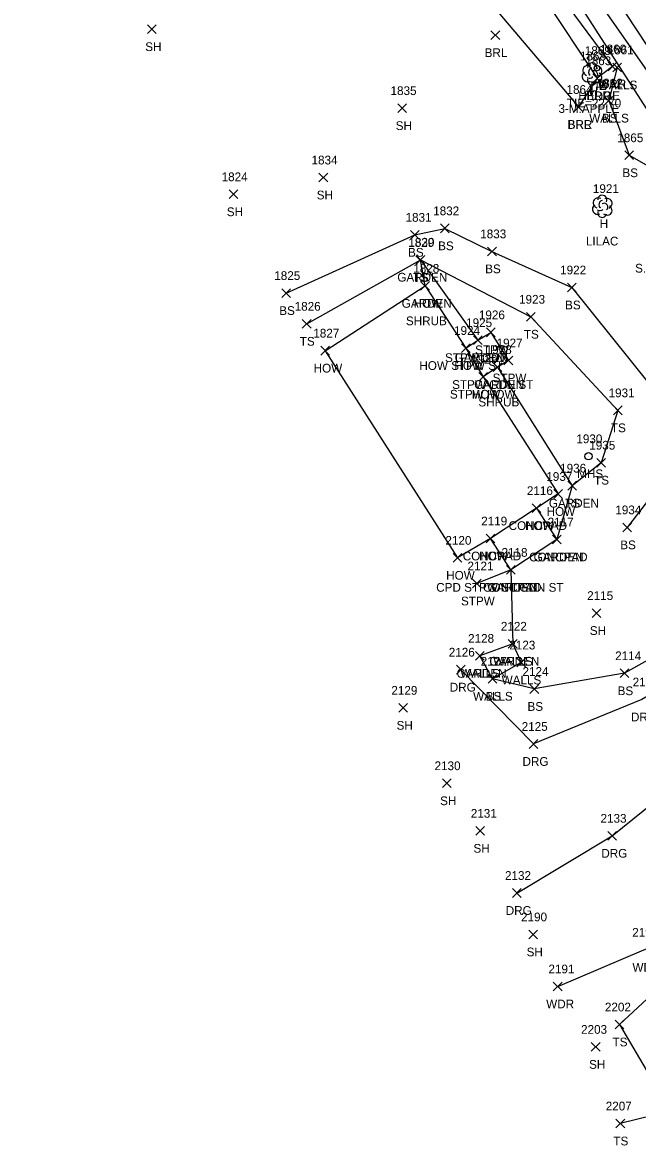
# Model space of a CAD drawing. Extents: x 1501299 to 1502485, y 381423 to 383765.
# Drawn here: x 1501332.8 to 1501473.5, y 383241.3 to 383498.2 of the extents above; entities that cross this region are included whole.
import ezdxf

# ---------------------------------------------------------------- set-up
doc = ezdxf.new("R2010")
doc.units = 0
for name, color, linetype in [('C_A', 7, 'Continuous'), ('C_C', 7, 'Continuous'), ('C_I', 7, 'Continuous'), ('CBP', 7, 'Continuous'), ('L_A', 7, 'Continuous'), ('L_C', 7, 'Continuous'), ('L_I', 7, 'Continuous'), ('L_TIC', 7, 'Continuous'), ('LABL', 7, 'Continuous'), ('LAHR', 7, 'Continuous'), ('LAPB', 7, 'Continuous'), ('LAWA', 7, 'Continuous'), ('LBC', 7, 'Continuous'), ('LBF', 7, 'Continuous'), ('LELB', 7, 'Continuous'), ('LS', 7, 'Continuous'), ('LTD', 7, 'Continuous'), ('LWS', 7, 'Continuous'), ('PET', 7, 'Continuous'), ('R_A', 7, 'Continuous'), ('R_I', 7, 'Continuous'), ('R_TIC', 7, 'Continuous'), ('RDG', 7, 'Continuous'), ('U_A', 7, 'Continuous'), ('U_I', 7, 'Continuous'), ('USMH', 7, 'Continuous')]:
    doc.layers.add(name, color=color, linetype=linetype)

msp = doc.modelspace()

# ---------------------------------------------------------------- linework, layer by layer
at = {"layer": 'CBP'}
for radius in [0.625, 0.0833]:
    msp.add_circle((1501464.19, 383487.75), radius, dxfattribs=at)
at = {"layer": 'L_TIC'}
for points in [[(1501361.38, 383495.65), (1501363.38, 383497.65)], [(1501363.38, 383495.65), (1501361.38, 383497.65)], [(1501439.97, 383494.28), (1501441.97, 383496.28)], [(1501441.97, 383494.28), (1501439.97, 383496.28)], [(1501466.78, 383487.13), (1501468.78, 383489.13)], [(1501468.78, 383487.13), (1501466.78, 383489.13)], [(1501467.85, 383486.89), (1501469.85, 383488.89)], [(1501469.85, 383486.89), (1501467.85, 383488.89)], [(1501463.27, 383484.42), (1501465.27, 383486.42)], [(1501465.27, 383484.42), (1501463.27, 383486.42)], [(1501463.27, 383484.42), (1501465.27, 383486.42)], [(1501465.27, 383484.42), (1501463.27, 383486.42)], [(1501418.68, 383477.59), (1501420.68, 383479.59)], [(1501420.68, 383477.59), (1501418.68, 383479.59)], [(1501458.99, 383477.86), (1501460.99, 383479.86)], [(1501460.99, 383477.86), (1501458.99, 383479.86)], [(1501458.99, 383477.86), (1501460.99, 383479.86)], [(1501460.99, 383477.86), (1501458.99, 383479.86)], [(1501465.9, 383479.31), (1501467.9, 383481.31)], [(1501467.9, 383479.31), (1501465.9, 383481.31)], [(1501465.9, 383479.31), (1501467.9, 383481.31)], [(1501467.9, 383479.31), (1501465.9, 383481.31)], [(1501470.6, 383466.81), (1501472.6, 383468.81)], [(1501472.6, 383466.81), (1501470.6, 383468.81)], [(1501400.61, 383461.72), (1501402.61, 383463.72)], [(1501402.61, 383461.72), (1501400.61, 383463.72)], [(1501380.04, 383457.89), (1501382.04, 383459.89)], [(1501382.04, 383457.89), (1501380.04, 383459.89)], [(1501428.44, 383450.1), (1501430.44, 383452.1)], [(1501430.44, 383450.1), (1501428.44, 383452.1)], [(1501421.55, 383448.61), (1501423.55, 383450.61)], [(1501423.55, 383448.61), (1501421.55, 383450.61)], [(1501439.2, 383444.83), (1501441.2, 383446.83)], [(1501441.2, 383444.83), (1501439.2, 383446.83)], [(1501422.74, 383442.85), (1501424.74, 383444.85)], [(1501424.74, 383442.85), (1501422.74, 383444.85)], [(1501422.87, 383442.92), (1501424.87, 383444.92)], [(1501424.87, 383442.92), (1501422.87, 383444.92)], [(1501422.87, 383442.92), (1501424.87, 383444.92)], [(1501424.87, 383442.92), (1501422.87, 383444.92)], [(1501423.88, 383436.94), (1501425.88, 383438.94)], [(1501425.88, 383436.94), (1501423.88, 383438.94)], [(1501423.88, 383436.94), (1501425.88, 383438.94)], [(1501425.88, 383436.94), (1501423.88, 383438.94)], [(1501457.48, 383436.57), (1501459.48, 383438.57)], [(1501459.48, 383436.57), (1501457.48, 383438.57)], [(1501392.09, 383435.29), (1501394.09, 383437.29)], [(1501394.09, 383435.29), (1501392.09, 383437.29)], [(1501448.08, 383429.87), (1501450.08, 383431.87)], [(1501450.08, 383429.87), (1501448.08, 383431.87)], [(1501396.81, 383428.26), (1501398.81, 383430.26)], [(1501398.81, 383428.26), (1501396.81, 383430.26)], [(1501438.94, 383426.31), (1501440.94, 383428.31)], [(1501440.94, 383426.31), (1501438.94, 383428.31)], [(1501435.98, 383424.52), (1501437.98, 383426.52)], [(1501437.98, 383424.52), (1501435.98, 383426.52)], [(1501435.98, 383424.52), (1501437.98, 383426.52)], [(1501437.98, 383424.52), (1501435.98, 383426.52)], [(1501401.01, 383422.12), (1501403.01, 383424.12)], [(1501403.01, 383422.12), (1501401.01, 383424.12)], [(1501401.01, 383422.12), (1501403.01, 383424.12)], [(1501403.01, 383422.12), (1501401.01, 383424.12)], [(1501433.21, 383422.72), (1501435.21, 383424.72)], [(1501435.21, 383422.72), (1501433.21, 383424.72)], [(1501433.21, 383422.72), (1501435.21, 383424.72)], [(1501435.21, 383422.72), (1501433.21, 383424.72)], [(1501442.94, 383419.88), (1501444.94, 383421.88)], [(1501444.94, 383419.88), (1501442.94, 383421.88)], [(1501437.21, 383416.16), (1501439.21, 383418.16)], [(1501439.21, 383416.16), (1501437.21, 383418.16)], [(1501437.21, 383416.16), (1501439.21, 383418.16)], [(1501439.21, 383416.16), (1501437.21, 383418.16)], [(1501440.46, 383418.37), (1501442.46, 383420.37)], [(1501442.46, 383418.37), (1501440.46, 383420.37)], [(1501440.46, 383418.37), (1501442.46, 383420.37)], [(1501442.46, 383418.37), (1501440.46, 383420.37)], [(1501468, 383408.47), (1501470, 383410.47)], [(1501470, 383408.47), (1501468, 383410.47)], [(1501464.15, 383396.49), (1501466.15, 383398.49)], [(1501466.15, 383396.49), (1501464.15, 383398.49)], [(1501457.54, 383391.24), (1501459.54, 383393.24)], [(1501459.54, 383391.24), (1501457.54, 383393.24)], [(1501457.54, 383391.24), (1501459.54, 383393.24)], [(1501459.54, 383391.24), (1501457.54, 383393.24)], [(1501454.32, 383389.34), (1501456.32, 383391.34)], [(1501456.32, 383389.34), (1501454.32, 383391.34)], [(1501449.36, 383386.1), (1501451.36, 383388.1)], [(1501451.36, 383386.1), (1501449.36, 383388.1)], [(1501449.36, 383386.1), (1501451.36, 383388.1)], [(1501451.36, 383386.1), (1501449.36, 383388.1)], [(1501470.1, 383381.7), (1501472.1, 383383.7)], [(1501472.1, 383381.7), (1501470.1, 383383.7)], [(1501438.87, 383379.15), (1501440.87, 383381.15)], [(1501440.87, 383379.15), (1501438.87, 383381.15)], [(1501438.87, 383379.15), (1501440.87, 383381.15)], [(1501440.87, 383379.15), (1501438.87, 383381.15)], [(1501454.06, 383378.92), (1501456.06, 383380.92)], [(1501456.06, 383378.92), (1501454.06, 383380.92)], [(1501454.06, 383378.92), (1501456.06, 383380.92)], [(1501456.06, 383378.92), (1501454.06, 383380.92)], [(1501431.33, 383374.73), (1501433.33, 383376.73)], [(1501433.33, 383374.73), (1501431.33, 383376.73)], [(1501431.33, 383374.73), (1501433.33, 383376.73)], [(1501433.33, 383374.73), (1501431.33, 383376.73)], [(1501443.51, 383371.98), (1501445.51, 383373.98)], [(1501445.51, 383371.98), (1501443.51, 383373.98)], [(1501443.51, 383371.98), (1501445.51, 383373.98)], [(1501445.51, 383371.98), (1501443.51, 383373.98)], [(1501443.51, 383371.98), (1501445.51, 383373.98)], [(1501445.51, 383371.98), (1501443.51, 383373.98)], [(1501435.72, 383368.86), (1501437.72, 383370.86)], [(1501437.72, 383368.86), (1501435.72, 383370.86)], [(1501463.09, 383362.1), (1501465.09, 383364.1)], [(1501465.09, 383362.1), (1501463.09, 383364.1)], [(1501443.93, 383355.08), (1501445.93, 383357.08)], [(1501445.93, 383355.08), (1501443.93, 383357.08)], [(1501443.93, 383355.08), (1501445.93, 383357.08)], [(1501445.93, 383355.08), (1501443.93, 383357.08)], [(1501436.42, 383352.31), (1501438.42, 383354.31)], [(1501438.42, 383352.31), (1501436.42, 383354.31)], [(1501436.42, 383352.31), (1501438.42, 383354.31)], [(1501438.42, 383352.31), (1501436.42, 383354.31)], [(1501445.87, 383350.78), (1501447.87, 383352.78)], [(1501447.87, 383350.78), (1501445.87, 383352.78)], [(1501439.32, 383347.07), (1501441.32, 383349.07)], [(1501441.32, 383347.07), (1501439.32, 383349.07)], [(1501439.32, 383347.07), (1501441.32, 383349.07)], [(1501441.32, 383347.07), (1501439.32, 383349.07)], [(1501469.5, 383348.33), (1501471.5, 383350.33)], [(1501471.5, 383348.33), (1501469.5, 383350.33)], [(1501448.88, 383344.74), (1501450.88, 383346.74)], [(1501450.88, 383344.74), (1501448.88, 383346.74)], [(1501418.88, 383340.42), (1501420.88, 383342.42)], [(1501420.88, 383340.42), (1501418.88, 383342.42)], [(1501428.84, 383323.17), (1501430.84, 383325.17)], [(1501430.84, 383323.17), (1501428.84, 383325.17)], [(1501436.47, 383312.29), (1501438.47, 383314.29)], [(1501438.47, 383312.29), (1501436.47, 383314.29)], [(1501448.63, 383288.59), (1501450.63, 383290.59)], [(1501450.63, 383288.59), (1501448.63, 383290.59)], [(1501454.23, 383276.69), (1501456.23, 383278.69)], [(1501456.23, 383276.69), (1501454.23, 383278.69)], [(1501468.37, 383267.99), (1501470.37, 383269.99)], [(1501470.37, 383267.99), (1501468.37, 383269.99)], [(1501462.92, 383262.87), (1501464.92, 383264.87)], [(1501464.92, 383262.87), (1501462.92, 383264.87)], [(1501468.56, 383245.34), (1501470.56, 383247.34)], [(1501470.56, 383245.34), (1501468.56, 383247.34)]]:
    msp.add_lwpolyline(points, dxfattribs=at)
at = {"layer": 'LABL'}
for points in [[(1501349.77, 383634.07), (1501358.61, 383636.91), (1501365.75, 383641.19), (1501375.86, 383617.1), (1501401.99, 383582.97), (1501432.56, 383539.71), (1501454.75, 383505.78), (1501467.78, 383488.13), (1501464.27, 383485.42), (1501459.99, 383478.86)], [(1501365.08, 383604.09), (1501372.27, 383598.02), (1501384.53, 383567.86), (1501459.99, 383478.86)]]:
    msp.add_lwpolyline(points, dxfattribs=at)
at = {"layer": 'LAHR'}
msp.add_lwpolyline([(1501432.56, 383539.71), (1501451.98, 383503.96), (1501464.27, 383485.42)], dxfattribs=at)
at = {"layer": 'LAPB'}
for points in [[(1501424.88, 383437.94), (1501423.87, 383443.92), (1501436.98, 383425.52)], [(1501441.46, 383419.37), (1501458.54, 383392.24), (1501455.06, 383379.92)], [(1501444.51, 383372.98), (1501444.93, 383356.08), (1501437.42, 383353.31)]]:
    msp.add_lwpolyline(points, dxfattribs=at)
at = {"layer": 'LAWA'}
msp.add_lwpolyline([(1501455.23, 383277.69), (1501474.97, 383286.07), (1501488.16, 383291.02), (1501505.3, 383294.67), (1501520.54, 383293.34), (1501529.9, 383294.53), (1501540.9, 383298.82), (1501560.18, 383293.04)], dxfattribs=at)
at = {"layer": 'LBC'}
for points in [[(1501402.01, 383423.12), (1501424.88, 383437.94), (1501434.21, 383423.72), (1501438.21, 383417.16), (1501455.32, 383390.34), (1501450.36, 383387.1), (1501439.87, 383380.15), (1501432.33, 383375.73)], [(1501402.01, 383423.12), (1501432.33, 383375.73)]]:
    msp.add_lwpolyline(points, dxfattribs=at)
at = {"layer": 'LBF'}
for points in [[(1501434.21, 383423.72), (1501436.98, 383425.52), (1501439.94, 383427.31), (1501443.94, 383420.88), (1501441.46, 383419.37), (1501438.21, 383417.16)], [(1501444.51, 383372.98), (1501436.72, 383369.86)]]:
    msp.add_lwpolyline(points, dxfattribs=at)
at = {"layer": 'LELB'}
for points in [[(1501332.79, 383719.08), (1501356.21, 383681.5), (1501373.29, 383652.69), (1501388.57, 383624.23), (1501410.59, 383588.65), (1501439.07, 383543.46), (1501460.07, 383509.46), (1501480.49, 383480.19), (1501499.63, 383452.74), (1501519.17, 383422.52), (1501533.38, 383399.88)], [(1501410.59, 383588.65), (1501435.97, 383541.32), (1501457.1, 383507.19), (1501476.16, 383477.48), (1501479.31, 383471.05), (1501488.94, 383457.91)], [(1501466.9, 383480.31), (1501471.6, 383467.81), (1501488.94, 383457.91), (1501495.79, 383450.81), (1501515.89, 383421.07), (1501517.94, 383408.26), (1501520.75, 383388.81), (1501512.36, 383377.31), (1501492.52, 383361.6), (1501470.5, 383349.33), (1501449.88, 383345.74), (1501440.32, 383348.07)], [(1501393.09, 383436.29), (1501422.55, 383449.61), (1501429.44, 383451.1), (1501440.2, 383445.83), (1501458.48, 383437.57), (1501476.43, 383415.16), (1501477.31, 383390.7), (1501471.1, 383382.7)], [(1501397.81, 383429.26), (1501423.74, 383443.85), (1501423.87, 383443.92), (1501449.08, 383430.87), (1501469, 383409.47), (1501465.15, 383397.49), (1501458.54, 383392.24)], [(1501529.79, 383319.02), (1501508.47, 383318.79), (1501498.45, 383314.16), (1501488.16, 383291.02), (1501493.84, 383282.99), (1501477.76, 383276.8), (1501469.37, 383268.99), (1501481.01, 383249.17), (1501469.56, 383246.34)]]:
    msp.add_lwpolyline(points, dxfattribs=at)
at = {"layer": 'LS'}
msp.add_lwpolyline([(1501450.36, 383387.1), (1501455.06, 383379.92), (1501444.51, 383372.98), (1501439.87, 383380.15)], dxfattribs=at)
at = {"layer": 'LTD'}
for p, q in [((1501463.06, 383486.5), (1501463.06, 383486.5)), ((1501463.06, 383486.5), (1501463.06, 383486.5)), ((1501465.41, 383456.18), (1501465.41, 383456.18)), ((1501465.41, 383456.18), (1501465.41, 383456.18))]:
    msp.add_line(p, q, dxfattribs=at)
for centre in [(1501463.11, 383487.94), (1501465.45, 383457.62)]:
    msp.add_arc(centre, 1.05, 335.5272, 180.9563, dxfattribs=at)
for centre, major_axis, ratio, start_param, end_param in [((1501462.27, 383487.17), (1.21, -0.51), 0.895232, 1.570796, 4.712389), ((1501462.85, 383486.96), (-0.208, -0.792), 0.645439, 3.141593, 6.283185), ((1501463.56, 383486.34), (-0.5, 0.667), 0.989748, 3.141593, 6.283185), ((1501464.1, 383487.09), (-1.14, -0.48), 0.949671, 1.570796, 4.712389), ((1501461.98, 383485.8), (0.58, -1.04), 0.959034, 3.141593, 6.283185), ((1501463.06, 383485), (0.26, 1.06), 0.942809, 1.570796, 4.712389), ((1501462.6, 383485.75), (-0.625, -0.083), 0.423636, 0, 3.141593), ((1501464.06, 383485.67), (-1.09, 0.79), 0.841452, 1.570796, 4.712389), ((1501464.32, 383455.47), (0.58, -1.04), 0.959034, 3.141593, 6.283185), ((1501464.62, 383456.85), (1.21, -0.51), 0.895232, 1.570796, 4.712389), ((1501465.2, 383456.64), (-0.208, -0.792), 0.645439, 3.141593, 6.283185), ((1501465.91, 383456.01), (-0.5, 0.667), 0.989748, 3.141593, 6.283185), ((1501466.45, 383456.76), (-1.14, -0.48), 0.949671, 1.570796, 4.712389), ((1501465.41, 383454.68), (0.26, 1.06), 0.942809, 1.570796, 4.712389), ((1501464.95, 383455.43), (-0.625, -0.083), 0.423636, 0, 3.141593), ((1501466.41, 383455.35), (-1.09, 0.79), 0.841452, 1.570796, 4.712389)]:
    msp.add_ellipse(centre, major_axis=major_axis, ratio=ratio, start_param=start_param, end_param=end_param, dxfattribs=at)
at = {"layer": 'LWS'}
for points in [[(1501468.85, 383487.89), (1501466.9, 383480.31)], [(1501444.93, 383356.08), (1501446.87, 383351.78), (1501440.32, 383348.07), (1501437.42, 383353.31)]]:
    msp.add_lwpolyline(points, dxfattribs=at)
at = {"layer": 'PET'}
msp.add_lwpolyline([(1501334.83, 383720.25), (1501358.01, 383682.47), (1501375.27, 383653.98), (1501391.81, 383626.28), (1501413.67, 383590.16), (1501441.93, 383545.3), (1501463.31, 383511.64), (1501483.05, 383481.71), (1501501.39, 383453.56), (1501521.79, 383422.95), (1501532.7, 383406.6), (1501560.32, 383365.3), (1501580.55, 383335.85), (1501587.21, 383326.16), (1501601.65, 383306.28)], dxfattribs=at)
at = {"layer": 'R_TIC'}
for points in [[(1501432.05, 383349.15), (1501434.05, 383351.15)], [(1501434.05, 383349.15), (1501432.05, 383351.15)], [(1501448.69, 383332.16), (1501450.69, 383334.16)], [(1501450.69, 383332.16), (1501448.69, 383334.16)], [(1501466.72, 383311.15), (1501468.72, 383313.15)], [(1501468.72, 383311.15), (1501466.72, 383313.15)], [(1501444.87, 383298.07), (1501446.87, 383300.07)], [(1501446.87, 383298.07), (1501444.87, 383300.07)]]:
    msp.add_lwpolyline(points, dxfattribs=at)
at = {"layer": 'RDG'}
for points in [[(1501532.7, 383406.6), (1501533.38, 383399.88), (1501528.17, 383386.85), (1501516.61, 383372.6), (1501496, 383355.77), (1501474.51, 383343.33), (1501449.69, 383333.16), (1501433.05, 383350.15)], [(1501445.87, 383299.07), (1501467.72, 383312.15), (1501488.93, 383329.33), (1501514.86, 383348.17), (1501534.19, 383361.88), (1501549.51, 383366.24), (1501560.32, 383365.3)]]:
    msp.add_lwpolyline(points, dxfattribs=at)
at = {"layer": 'USMH'}
for p, q in [((1501462.28, 383398.96), (1501462.28, 383398.96)), ((1501463.11, 383398.96), (1501463.11, 383398.96))]:
    msp.add_line(p, q, dxfattribs=at)
msp.add_circle((1501462.28, 383398.96), 0.833, dxfattribs=at)

# ---------------------------------------------------------------- texts
at = {"layer": 'C_A'}
msp.add_text('TIE', height=2, dxfattribs=at).set_placement((1501462.27, 383482.75))
at = {"layer": 'C_C'}
msp.add_text('TIE=22.70', height=2, dxfattribs=at).set_placement((1501457.33, 383478.75))
at = {"layer": 'C_I'}
msp.add_text('1869', height=2, dxfattribs=at).set_placement((1501461.44, 383490.75))
at = {"layer": 'L_A'}
for s, p in [('SH', (1501360.87, 383491.65)), ('BRL', (1501438.52, 383490.28)), ('WALLS', (1501464.39, 383482.89)), ('BRR', (1501465.26, 383483.13)), ('HEDGE', (1501459.97, 383480.42)), ('BRR', (1501461.76, 383480.42)), ('H', (1501462.5, 383481.5)), ('WALLS', (1501462.45, 383475.31)), ('BS', (1501465.34, 383475.31)), ('SH', (1501418.17, 383473.59)), ('BRR', (1501457.48, 383473.86)), ('BRL', (1501457.54, 383473.86)), ('BS', (1501470.04, 383462.81)), ('SH', (1501400.1, 383457.72)), ('SH', (1501379.53, 383453.89)), ('H', (1501464.84, 383451.18)), ('BS', (1501421, 383444.61)), ('BS', (1501427.88, 383446.1)), ('BS', (1501438.64, 383440.83)), ('GARDEN', (1501418.54, 383438.92)), ('TS', (1501422.15, 383438.85)), ('TS', (1501422.28, 383438.92)), ('BS', (1501391.53, 383431.29)), ('GARDEN', (1501419.55, 383432.94)), ('HOW', (1501422.27, 383432.94)), ('BS', (1501456.92, 383432.57)), ('TS', (1501396.22, 383424.26)), ('TS', (1501447.49, 383425.87)), ('STPW', (1501436.34, 383422.31)), ('HOW STPW ST', (1501423.59, 383418.72)), ('STPW GDN', (1501429.46, 383420.52)), ('GARDEN', (1501431.65, 383420.52)), ('HOW', (1501431.6, 383418.72)), ('HOW', (1501399.4, 383418.12)), ('HOW', (1501399.4, 383418.12)), ('STPW', (1501440.34, 383415.88)), ('STPW GDN ST', (1501431.08, 383414.37)), ('GARDEN', (1501436.13, 383414.37)), ('STPW HOW', (1501430.58, 383412.16)), ('HOW', (1501435.59, 383412.16)), ('TS', (1501467.41, 383404.47)), ('TS', (1501463.56, 383392.49)), ('HOW', (1501452.7, 383385.34)), ('GARDEN', (1501453.21, 383387.24)), ('TS', (1501456.95, 383387.24)), ('CONCPAD', (1501444.01, 383382.1)), ('HOW', (1501447.75, 383382.1)), ('BS', (1501469.54, 383377.7)), ('CONCPAD', (1501433.51, 383375.15)), ('HOW', (1501437.25, 383375.15)), ('CONCPAD', (1501448.7, 383374.92)), ('GARDEN', (1501449.73, 383374.92)), ('HOW', (1501429.72, 383370.73)), ('HOW', (1501429.72, 383370.73)), ('CPD STPW ST GDN ST', (1501427.44, 383367.98)), ('CONCPAD', (1501438.15, 383367.98)), ('GARDEN', (1501439.18, 383367.98)), ('STPW', (1501433.11, 383364.86)), ('SH', (1501462.58, 383358.1)), ('GARDEN', (1501439.6, 383351.08)), ('WALLS', (1501440.47, 383351.08)), ('GARDEN', (1501432.09, 383348.31)), ('WALLS', (1501432.96, 383348.31)), ('WALLS', (1501442.41, 383346.78)), ('BS', (1501468.94, 383344.33)), ('WALLS', (1501435.87, 383343.07)), ('BS', (1501438.76, 383343.07)), ('BS', (1501448.32, 383340.74)), ('SH', (1501418.37, 383336.42)), ('SH', (1501428.33, 383319.17)), ('SH', (1501435.96, 383308.29)), ('SH', (1501448.12, 383284.59)), ('WDR', (1501472.33, 383281.07)), ('WDR', (1501452.6, 383272.69)), ('TS', (1501467.78, 383263.99)), ('SH', (1501462.41, 383258.87)), ('TS', (1501467.97, 383241.34))]:
    msp.add_text(s, height=2, dxfattribs=at).set_placement(p)
at = {"layer": 'L_C'}
for s, p in [('3-M.APPLE', (1501455.41, 383477.5)), ('LILAC', (1501461.68, 383447.18)), ('S.MAPLE', (1501472.94, 383440.98)), ('SHRUB', (1501420.51, 383428.94)), ('SHRUB', (1501437.09, 383410.37))]:
    msp.add_text(s, height=2, dxfattribs=at).set_placement(p)
at = {"layer": 'L_I'}
for s, p in [('1860', (1501464.95, 383491.13)), ('1861', (1501466.67, 383490.89)), ('1868', (1501460.32, 383489.5)), ('1863', (1501461.53, 383488.42)), ('1863', (1501461.53, 383488.42)), ('1862', (1501464.16, 383483.31)), ('1862', (1501464.16, 383483.31)), ('1835', (1501416.99, 383481.59)), ('1864', (1501457.25, 383481.86)), ('1864', (1501457.25, 383481.86)), ('1865', (1501468.86, 383470.81)), ('1834', (1501398.92, 383465.72)), ('1824', (1501378.35, 383461.89)), ('1921', (1501463.28, 383459.18)), ('1831', (1501420.43, 383452.61)), ('1832', (1501426.75, 383454.1)), ('1829', (1501421.04, 383446.85)), ('1830', (1501421.09, 383446.92)), ('1830', (1501421.09, 383446.92)), ('1833', (1501437.51, 383448.83)), ('1825', (1501390.39, 383439.29)), ('1828', (1501422.19, 383440.94)), ('1828', (1501422.19, 383440.94)), ('1922', (1501455.79, 383440.57)), ('1923', (1501446.39, 383433.87)), ('1826', (1501395.06, 383432.26)), ('1926', (1501437.2, 383430.31)), ('1827', (1501399.32, 383426.12)), ('1827', (1501399.32, 383426.12)), ('1924', (1501431.52, 383426.72)), ('1924', (1501431.52, 383426.72)), ('1925', (1501434.28, 383428.52)), ('1925', (1501434.28, 383428.52)), ('1927', (1501441.25, 383423.88)), ('1928', (1501438.77, 383422.37)), ('1928', (1501438.77, 383422.37)), ('1929', (1501435.5, 383420.16)), ('1929', (1501435.5, 383420.16)), ('1931', (1501466.87, 383412.47)), ('1935', (1501462.45, 383400.49)), ('1937', (1501452.63, 383393.34)), ('1936', (1501455.79, 383395.24)), ('1936', (1501455.79, 383395.24)), ('2116', (1501448.18, 383390.1)), ('2116', (1501448.18, 383390.1)), ('1934', (1501468.41, 383385.7)), ('2119', (1501437.73, 383383.15)), ('2119', (1501437.73, 383383.15)), ('2117', (1501452.93, 383382.92)), ('2117', (1501452.93, 383382.92)), ('2120', (1501429.55, 383378.73)), ('2120', (1501429.55, 383378.73)), ('2118', (1501442.38, 383375.98)), ('2118', (1501442.38, 383375.98)), ('2118', (1501442.38, 383375.98)), ('2121', (1501434.59, 383372.86)), ('2115', (1501461.97, 383366.1)), ('2122', (1501442.23, 383359.08)), ('2122', (1501442.23, 383359.08)), ('2128', (1501434.73, 383356.31)), ('2128', (1501434.73, 383356.31)), ('2123', (1501444.17, 383354.78)), ('2114', (1501468.38, 383352.33)), ('2127', (1501437.63, 383351.07)), ('2127', (1501437.63, 383351.07)), ('2124', (1501447.18, 383348.74)), ('2129', (1501417.18, 383344.42)), ('2130', (1501427.06, 383327.17)), ('2131', (1501435.35, 383316.29)), ('2190', (1501446.85, 383292.59)), ('2192', (1501472.28, 383289.07)), ('2191', (1501453.11, 383280.69)), ('2202', (1501466.03, 383271.99)), ('2203', (1501460.58, 383266.87)), ('2207', (1501466.22, 383249.34))]:
    msp.add_text(s, height=2, dxfattribs=at).set_placement(p)
at = {"layer": 'R_A'}
for p in [(1501430.54, 383345.15), (1501472, 383338.33), (1501447.18, 383328.16), (1501465.21, 383307.15), (1501443.35, 383294.07)]:
    msp.add_text('DRG', height=2, dxfattribs=at).set_placement(p)
at = {"layer": 'R_I'}
for s, p in [('2126', (1501430.31, 383353.15)), ('2113', (1501472.38, 383346.33)), ('2125', (1501447, 383336.16)), ('2133', (1501465.03, 383315.15)), ('2132', (1501443.17, 383302.07))]:
    msp.add_text(s, height=2, dxfattribs=at).set_placement(p)
at = {"layer": 'U_A'}
msp.add_text('MHS', height=2, dxfattribs=at).set_placement((1501459.69, 383393.96))
at = {"layer": 'U_I'}
msp.add_text('1930', height=2, dxfattribs=at).set_placement((1501459.5, 383401.96))

doc.saveas('drawing.dxf')
